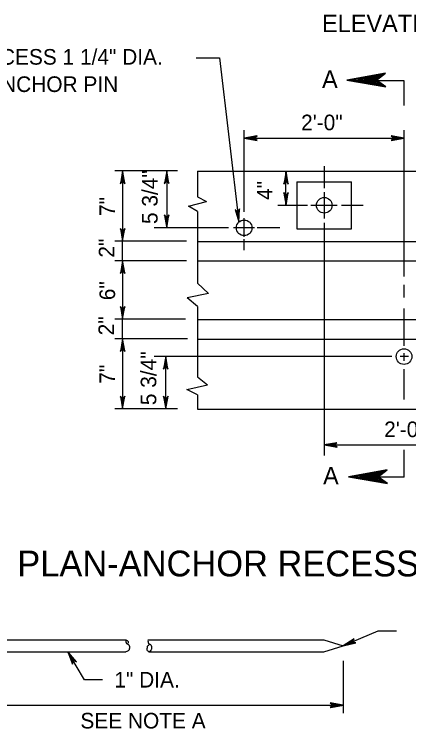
# Model space of a CAD drawing. Extents: x 499883 to 500983, y 499104 to 499764.
# Drawn here: x 500034.1 to 500135.2, y 499385.9 to 499568.8 of the extents above; entities that cross this region are included whole.
import ezdxf

# ---------------------------------------------------------------- set-up
doc = ezdxf.new("R2010")
doc.units = 0
doc.layers.add('24', color=7, linetype='Continuous')
doc.layers.add('5', color=7, linetype='Continuous')

msp = doc.modelspace()

# ---------------------------------------------------------------- linework, layer by layer
at = {"layer": '24'}
for points in [[(500061.83, 499528.7), (500061.25, 499525.43), (500061.83, 499526.21), (500062.4, 499525.44), (500061.83, 499528.7), (500061.84, 499528.48), (500061.3, 499525.52), (500061.84, 499526.27), (500062.36, 499525.58), (500061.85, 499528.37), (500061.83, 499528.26), (500061.38, 499525.72), (500061.84, 499526.29), (500062.28, 499525.7), (500061.83, 499528.21), (500061.85, 499528.1), (500061.45, 499525.88), (500061.83, 499526.31), (500062.23, 499525.87), (500061.85, 499527.78), (500061.85, 499527.6), (500061.53, 499526.04), (500061.82, 499526.35), (500062.15, 499526.02), (500061.83, 499527.56), (500061.82, 499527.39), (500061.62, 499526.22), (500061.85, 499526.45), (500062.07, 499526.2), (500061.83, 499527.23), (500061.82, 499527.06), (500061.68, 499526.36), (500061.84, 499526.48), (500062.01, 499526.29), (500061.83, 499526.98), (500061.72, 499526.52), (500061.85, 499526.59), (500061.97, 499526.39), (500061.85, 499526.86), (500061.77, 499526.56), (500061.87, 499526.69), (500061.93, 499526.54), (500061.84, 499526.69), (500061.82, 499526.61)], [(500103.72, 499528.63), (500103.13, 499525.31), (500103.72, 499526.1), (500104.29, 499525.32), (500103.72, 499528.63), (500103.72, 499528.41), (500103.17, 499525.4), (500103.72, 499526.16), (500104.25, 499525.46), (500103.73, 499528.29), (500103.72, 499528.18), (500103.26, 499525.6), (500103.72, 499526.18), (500104.17, 499525.59), (500103.71, 499528.13), (500103.73, 499528.02), (500103.33, 499525.77), (500103.71, 499526.2), (500104.12, 499525.76), (500103.73, 499527.7), (500103.73, 499527.51), (500103.41, 499525.93), (500103.71, 499526.24), (500104.04, 499525.91), (500103.72, 499527.48), (500103.71, 499527.3), (500103.5, 499526.11), (500103.73, 499526.34), (500103.96, 499526.09), (500103.72, 499527.14), (500103.7, 499526.97), (500103.56, 499526.26), (500103.72, 499526.37), (500103.9, 499526.18), (500103.71, 499526.88), (500103.6, 499526.42), (500103.73, 499526.49), (500103.86, 499526.28), (500103.73, 499526.77), (500103.66, 499526.46), (500103.76, 499526.59), (500103.82, 499526.44), (500103.72, 499526.59), (500103.71, 499526.51)], [(500103.72, 499519.87), (500104.3, 499523.19), (500103.72, 499522.4), (500103.14, 499523.18), (500103.72, 499519.87), (500103.71, 499520.09), (500104.26, 499523.1), (500103.71, 499522.34), (500103.18, 499523.04), (500103.7, 499520.21), (500103.72, 499520.32), (500104.17, 499522.9), (500103.71, 499522.32), (500103.26, 499522.91), (500103.72, 499520.37), (500103.7, 499520.48), (500104.11, 499522.73), (500103.72, 499522.3), (500103.31, 499522.74), (500103.7, 499520.8), (500103.7, 499520.99), (500104.02, 499522.57), (500103.73, 499522.26), (500103.39, 499522.59), (500103.72, 499521.02), (500103.73, 499521.2), (500103.93, 499522.39), (500103.7, 499522.16), (500103.47, 499522.41), (500103.72, 499521.36), (500103.73, 499521.53), (500103.87, 499522.24), (500103.71, 499522.13), (500103.53, 499522.32), (500103.72, 499521.62), (500103.83, 499522.08), (500103.7, 499522.01), (500103.57, 499522.22), (500103.7, 499521.73), (500103.78, 499522.04), (500103.67, 499521.91), (500103.61, 499522.06), (500103.71, 499521.91), (500103.73, 499521.99)], [(500091.63, 499515.65), (500091.82, 499518.97), (500091.34, 499518.12), (500090.68, 499518.82), (500091.63, 499515.65), (500091.6, 499515.86), (500091.79, 499518.87), (500091.34, 499518.06), (500090.74, 499518.69), (500091.57, 499515.98), (500091.58, 499516.09), (500091.73, 499518.66), (500091.34, 499518.04), (500090.83, 499518.57), (500091.57, 499516.14), (500091.54, 499516.24), (500091.68, 499518.5), (500091.35, 499518.02), (500090.9, 499518.41), (500091.51, 499516.56), (500091.48, 499516.74), (500091.62, 499518.32), (500091.36, 499517.99), (500091, 499518.27), (500091.5, 499516.78), (500091.49, 499516.95), (500091.55, 499518.14), (500091.35, 499517.89), (500091.1, 499518.1), (500091.46, 499517.11), (500091.46, 499517.28), (500091.51, 499517.99), (500091.36, 499517.85), (500091.17, 499518.02), (500091.43, 499517.36), (500091.48, 499517.83), (500091.37, 499517.75), (500091.22, 499517.93), (500091.4, 499517.47), (500091.44, 499517.78), (500091.36, 499517.64), (500091.28, 499517.78), (500091.39, 499517.65), (500091.4, 499517.72)], [(500061.83, 499510.71), (500062.41, 499513.99), (500061.83, 499513.21), (500061.26, 499513.97), (500061.83, 499510.71), (500061.83, 499510.93), (500062.37, 499513.9), (500061.83, 499513.15), (500061.31, 499513.84), (500061.82, 499511.05), (500061.83, 499511.16), (500062.28, 499513.7), (500061.83, 499513.13), (500061.38, 499513.71), (500061.83, 499511.21), (500061.82, 499511.32), (500062.22, 499513.54), (500061.83, 499513.11), (500061.43, 499513.55), (500061.82, 499511.63), (500061.82, 499511.82), (500062.13, 499513.37), (500061.84, 499513.07), (500061.52, 499513.4), (500061.83, 499511.85), (500061.84, 499512.03), (500062.04, 499513.19), (500061.82, 499512.97), (500061.59, 499513.21), (500061.83, 499512.19), (500061.85, 499512.35), (500061.98, 499513.05), (500061.83, 499512.94), (500061.65, 499513.13), (500061.83, 499512.44), (500061.94, 499512.89), (500061.82, 499512.83), (500061.69, 499513.03), (500061.82, 499512.55), (500061.89, 499512.85), (500061.79, 499512.73), (500061.73, 499512.87), (500061.83, 499512.73), (500061.84, 499512.8)], [(500061.83, 499505.72), (500061.25, 499502.44), (500061.83, 499503.23), (500062.4, 499502.46), (500061.83, 499505.72), (500061.84, 499505.5), (500061.3, 499502.54), (500061.84, 499503.29), (500062.36, 499502.59), (500061.85, 499505.38), (500061.83, 499505.27), (500061.38, 499502.73), (500061.84, 499503.3), (500062.28, 499502.72), (500061.83, 499505.22), (500061.85, 499505.12), (500061.45, 499502.9), (500061.83, 499503.33), (500062.23, 499502.89), (500061.85, 499504.8), (500061.85, 499504.61), (500061.53, 499503.06), (500061.82, 499503.36), (500062.15, 499503.04), (500061.83, 499504.58), (500061.82, 499504.41), (500061.62, 499503.24), (500061.85, 499503.46), (500062.07, 499503.22), (500061.83, 499504.25), (500061.82, 499504.08), (500061.68, 499503.38), (500061.84, 499503.5), (500062.01, 499503.3), (500061.83, 499504), (500061.72, 499503.54), (500061.85, 499503.6), (500061.97, 499503.4), (500061.85, 499503.88), (500061.77, 499503.58), (500061.87, 499503.71), (500061.93, 499503.56), (500061.84, 499503.71), (500061.82, 499503.63)], [(500061.83, 499490.73), (500062.41, 499494), (500061.83, 499493.22), (500061.26, 499493.99), (500061.83, 499490.73), (500061.83, 499490.95), (500062.37, 499493.91), (500061.83, 499493.16), (500061.31, 499493.85), (500061.82, 499491.06), (500061.83, 499491.17), (500062.28, 499493.71), (500061.83, 499493.14), (500061.38, 499493.73), (500061.83, 499491.22), (500061.82, 499491.33), (500062.22, 499493.55), (500061.83, 499493.12), (500061.43, 499493.56), (500061.82, 499491.65), (500061.82, 499491.83), (500062.13, 499493.39), (500061.84, 499493.09), (500061.52, 499493.41), (500061.83, 499491.87), (500061.84, 499492.04), (500062.04, 499493.21), (500061.82, 499492.98), (500061.59, 499493.23), (500061.83, 499492.2), (500061.85, 499492.37), (500061.98, 499493.07), (500061.83, 499492.95), (500061.65, 499493.14), (500061.83, 499492.45), (500061.94, 499492.91), (500061.82, 499492.84), (500061.69, 499493.04), (500061.82, 499492.57), (500061.89, 499492.87), (500061.79, 499492.74), (500061.73, 499492.89), (500061.83, 499492.74), (500061.84, 499492.82)], [(500061.83, 499485.73), (500061.25, 499482.46), (500061.83, 499483.24), (500062.4, 499482.48), (500061.83, 499485.73), (500061.84, 499485.52), (500061.3, 499482.55), (500061.84, 499483.3), (500062.36, 499482.61), (500061.85, 499485.4), (500061.83, 499485.29), (500061.38, 499482.75), (500061.84, 499483.32), (500062.28, 499482.73), (500061.83, 499485.24), (500061.85, 499485.13), (500061.45, 499482.91), (500061.83, 499483.34), (500062.23, 499482.9), (500061.85, 499484.82), (500061.85, 499484.63), (500061.53, 499483.08), (500061.82, 499483.38), (500062.15, 499483.05), (500061.83, 499484.6), (500061.82, 499484.42), (500061.62, 499483.25), (500061.85, 499483.48), (500062.07, 499483.23), (500061.83, 499484.26), (500061.82, 499484.1), (500061.68, 499483.39), (500061.84, 499483.51), (500062.01, 499483.32), (500061.83, 499484.01), (500061.72, 499483.55), (500061.85, 499483.62), (500061.97, 499483.42), (500061.85, 499483.9), (500061.77, 499483.6), (500061.87, 499483.72), (500061.93, 499483.58), (500061.84, 499483.72), (500061.82, 499483.65)], [(500061.83, 499467.75), (500062.41, 499471.02), (500061.83, 499470.24), (500061.26, 499471), (500061.83, 499467.75), (500061.83, 499467.96), (500062.37, 499470.93), (500061.83, 499470.18), (500061.31, 499470.87), (500061.82, 499468.08), (500061.83, 499468.19), (500062.28, 499470.73), (500061.83, 499470.16), (500061.38, 499470.75), (500061.83, 499468.24), (500061.82, 499468.35), (500062.22, 499470.57), (500061.83, 499470.14), (500061.43, 499470.58), (500061.82, 499468.67), (500061.82, 499468.85), (500062.13, 499470.41), (500061.84, 499470.1), (500061.52, 499470.43), (500061.83, 499468.88), (500061.84, 499469.06), (500062.04, 499470.23), (500061.82, 499470), (500061.59, 499470.25), (500061.83, 499469.22), (500061.85, 499469.38), (500061.98, 499470.09), (500061.83, 499469.97), (500061.65, 499470.16), (500061.83, 499469.47), (500061.94, 499469.93), (500061.82, 499469.86), (500061.69, 499470.06), (500061.82, 499469.58), (500061.89, 499469.89), (500061.79, 499469.76), (500061.73, 499469.9), (500061.83, 499469.76), (500061.84, 499469.84)], [(500113.51, 499458.54), (500116.79, 499457.96), (500116, 499458.54), (500116.77, 499459.11), (500113.51, 499458.54), (500113.73, 499458.54), (500116.7, 499458), (500115.94, 499458.55), (500116.64, 499459.06), (500113.85, 499458.55), (500113.96, 499458.54), (500116.5, 499458.09), (500115.93, 499458.55), (500116.51, 499458.99), (500114.01, 499458.54), (500114.12, 499458.55), (500116.34, 499458.15), (500115.9, 499458.54), (500116.34, 499458.94), (500114.43, 499458.56), (500114.62, 499458.55), (500116.17, 499458.24), (500115.87, 499458.53), (500116.19, 499458.85), (500114.65, 499458.54), (500114.82, 499458.53), (500115.99, 499458.33), (500115.77, 499458.56), (500116.01, 499458.78), (500114.98, 499458.54), (500115.15, 499458.52), (500115.85, 499458.39), (500115.74, 499458.55), (500115.93, 499458.72), (500115.23, 499458.54), (500115.69, 499458.43), (500115.63, 499458.55), (500115.83, 499458.68), (500115.35, 499458.56), (500115.65, 499458.48), (500115.52, 499458.58), (500115.67, 499458.64), (500115.53, 499458.55), (500115.6, 499458.53)], [(500118.39, 499407.09), (500121.63, 499407.84), (500120.69, 499408.07), (500121.17, 499408.89), (500118.39, 499407.09), (500118.59, 499407.18), (500121.53, 499407.85), (500120.63, 499408.05), (500121.06, 499408.8), (500118.7, 499407.23), (500118.8, 499407.26), (500121.31, 499407.85), (500120.61, 499408.04), (500120.98, 499408.68), (500118.85, 499407.28), (500118.94, 499407.34), (500121.14, 499407.84), (500120.59, 499408.03), (500120.84, 499408.57), (500119.23, 499407.46), (500119.4, 499407.54), (500120.96, 499407.86), (500120.56, 499408.01), (500120.74, 499408.43), (500119.44, 499407.54), (500119.6, 499407.59), (500120.76, 499407.87), (500120.46, 499407.99), (500120.6, 499408.29), (500119.75, 499407.67), (500119.91, 499407.72), (500120.6, 499407.87), (500120.44, 499407.97), (500120.54, 499408.2), (500119.98, 499407.77), (500120.44, 499407.84), (500120.33, 499407.93), (500120.47, 499408.13), (500120.08, 499407.83), (500120.38, 499407.87), (500120.23, 499407.92), (500120.34, 499408.03), (500120.24, 499407.89), (500120.32, 499407.9)], [(500047.83, 499405.59), (500049.02, 499402.4), (500049.12, 499403.39), (500050.02, 499403.01), (500047.83, 499405.59), (500047.95, 499405.4), (500049.01, 499402.51), (500049.1, 499403.45), (500049.92, 499403.11), (500048.02, 499405.3), (500048.06, 499405.2), (500048.98, 499402.72), (500049.09, 499403.46), (500049.79, 499403.18), (500048.09, 499405.15), (500048.16, 499405.07), (500048.96, 499402.9), (500049.07, 499403.48), (500049.65, 499403.3), (500048.32, 499404.79), (500048.42, 499404.63), (500048.94, 499403.09), (500049.05, 499403.51), (500049.5, 499403.39), (500048.42, 499404.59), (500048.5, 499404.43), (500048.93, 499403.29), (500049.02, 499403.61), (500049.34, 499403.51), (500048.59, 499404.29), (500048.67, 499404.14), (500048.91, 499403.45), (500048.99, 499403.63), (500049.24, 499403.56), (500048.72, 499404.07), (500048.87, 499403.61), (500048.94, 499403.73), (500049.16, 499403.62), (500048.8, 499403.98), (500048.89, 499403.67), (500048.91, 499403.84), (500049.04, 499403.74), (500048.88, 499403.82), (500048.91, 499403.74)], [(500118.39, 499391.86), (500115.04, 499392.45), (500115.84, 499391.86), (500115.06, 499391.27), (500118.39, 499391.86), (500118.17, 499391.85), (500115.14, 499392.4), (500115.91, 499391.85), (500115.2, 499391.32), (500118.05, 499391.84), (500117.94, 499391.86), (500115.34, 499392.32), (500115.92, 499391.85), (500115.32, 499391.39), (500117.89, 499391.86), (500117.78, 499391.84), (500115.51, 499392.25), (500115.95, 499391.86), (500115.5, 499391.45), (500117.45, 499391.84), (500117.27, 499391.84), (500115.67, 499392.16), (500115.98, 499391.86), (500115.65, 499391.53), (500117.23, 499391.86), (500117.05, 499391.87), (500115.86, 499392.07), (500116.09, 499391.84), (500115.84, 499391.61), (500116.89, 499391.86), (500116.72, 499391.87), (500116, 499392.01), (500116.12, 499391.85), (500115.92, 499391.67), (500116.63, 499391.86), (500116.16, 499391.97), (500116.23, 499391.84), (500116.03, 499391.71), (500116.51, 499391.84), (500116.21, 499391.92), (500116.34, 499391.81), (500116.19, 499391.75), (500116.33, 499391.85), (500116.26, 499391.86)]]:
    msp.add_lwpolyline(points, dxfattribs=at)
at = {"layer": '5'}
for p, q in [((500133.95, 499551.76), (500123.96, 499551.76)), ((500133.95, 499545.45), (500133.95, 499551.76)), ((500092.98, 499518.26), (500092.98, 499539.12)), ((500133.95, 499501.67), (500133.95, 499539.12)), ((500092.98, 499537.13), (500133.95, 499537.13)), ((500075.88, 499528.7), (500059.85, 499528.7)), ((500061.83, 499528.7), (500061.83, 499510.71)), ((500073.13, 499528.7), (500073.13, 499514.14)), ((500080.99, 499528.63), (500170.92, 499528.63)), ((500080.99, 499528.63), (500080.99, 499522.12)), ((500103.7, 499519.91), (500103.7, 499528.63)), ((500113.51, 499529.9), (500113.51, 499524.3)), ((500106.52, 499525.91), (500120.51, 499525.91)), ((500106.52, 499525.91), (500106.52, 499513.92)), ((500120.51, 499513.92), (500120.51, 499525.91)), ((500113.51, 499523.24), (500113.51, 499516.55)), ((500080.99, 499522.12), (500083.29, 499520.89)), ((500078.68, 499519.67), (500083.29, 499520.89)), ((500080.99, 499518.32), (500078.68, 499519.67)), ((500101.6, 499519.91), (500109.22, 499519.91)), ((500110.07, 499519.91), (500116.85, 499519.91)), ((500117.91, 499519.91), (500123.51, 499519.91)), ((500080.99, 499518.32), (500080.99, 499500)), ((500092.98, 499511.81), (500092.98, 499516.63)), ((500088.97, 499514.14), (500069.93, 499514.14)), ((500095.59, 499514.14), (500090.28, 499514.14)), ((500102.15, 499514.14), (500096.32, 499514.14)), ((500106.52, 499513.92), (500120.51, 499513.92)), ((500113.51, 499515.39), (500113.51, 499455.84)), ((500078.21, 499510.71), (500059.85, 499510.71)), ((500061.83, 499505.76), (500061.83, 499510.71)), ((500080.99, 499510.65), (500170.92, 499510.65)), ((500092.98, 499508.41), (500092.98, 499511.23)), ((500078.21, 499505.72), (500059.85, 499505.72)), ((500061.83, 499505.72), (500061.83, 499490.73)), ((500080.99, 499505.65), (500170.92, 499505.65)), ((500080.99, 499500), (500083.84, 499497.29)), ((500133.95, 499496.26), (500133.95, 499499.57)), ((500083.84, 499497.29), (500078.41, 499496.2)), ((500080.99, 499494.03), (500078.41, 499496.2)), ((500080.99, 499494.03), (500080.99, 499475.98)), ((500133.95, 499483.95), (500133.95, 499493.51)), ((500077.96, 499490.73), (500059.85, 499490.73)), ((500061.83, 499485.73), (500061.83, 499490.73)), ((500080.99, 499490.66), (500170.92, 499490.66)), ((500078.46, 499485.73), (500059.85, 499485.73)), ((500061.83, 499485.73), (500061.83, 499467.75)), ((500080.99, 499485.66), (500170.92, 499485.66)), ((500130.83, 499481.17), (500069.93, 499481.17)), ((500072.88, 499467.75), (500072.88, 499481.24)), ((500135.13, 499481.17), (500132.93, 499481.17)), ((500133.95, 499480.05), (500133.95, 499482.05)), ((500133.95, 499470.15), (500133.95, 499477.95)), ((500080.99, 499475.98), (500083.56, 499473.95)), ((500078.27, 499472.73), (500083.56, 499473.95)), ((500080.99, 499471.37), (500078.27, 499472.73)), ((500080.99, 499471.37), (500080.99, 499467.68)), ((500075.88, 499467.75), (500059.85, 499467.75)), ((500080.99, 499467.68), (500170.92, 499467.68)), ((500113.51, 499458.54), (500155.99, 499458.54)), ((500133.95, 499450.26), (500133.95, 499457.32)), ((500133.95, 499450.26), (500123.96, 499450.26)), ((500020.47, 499408.59), (500062.68, 499408.59)), ((500068.34, 499408.59), (500113.4, 499408.59)), ((500113.4, 499408.59), (500118.39, 499407.09)), ((500113.4, 499405.59), (500118.39, 499407.09)), ((500020.47, 499405.59), (500062.68, 499405.59)), ((500068.55, 499405.59), (500113.4, 499405.59)), ((500118.39, 499403.22), (500118.39, 499389.86)), ((500056.71, 499398.41), (500052.06, 499398.41)), ((500018.97, 499391.86), (500118.39, 499391.86))]:
    msp.add_line(p, q, dxfattribs=at)
for points in [[(500080.64, 499557.71), (500086.7, 499557.71), (500091.63, 499515.65)], [(500119.27, 499551.99), (500129.25, 499550.23), (500126.86, 499551.99), (500129.19, 499553.72), (500119.27, 499551.99), (500119.94, 499552.01), (500128.97, 499550.36), (500126.68, 499552.01), (500128.79, 499553.59), (500120.29, 499552.04), (500120.63, 499551.99), (500128.36, 499550.61), (500126.63, 499552.01), (500128.41, 499553.36), (500120.78, 499551.99), (500121.11, 499552.04), (500127.87, 499550.82), (500126.55, 499551.99), (500127.9, 499553.21), (500122.07, 499552.04), (500122.63, 499552.04), (500127.37, 499551.07), (500126.45, 499551.96), (500127.44, 499552.95), (500122.73, 499551.99), (500123.27, 499551.96), (500126.83, 499551.35), (500126.14, 499552.04), (500126.88, 499552.72), (500123.76, 499551.99), (500124.26, 499551.94), (500126.4, 499551.53), (500126.04, 499552.01), (500126.63, 499552.54), (500124.52, 499551.99), (500125.91, 499551.66), (500125.71, 499552.04), (500126.32, 499552.42), (500124.87, 499552.04), (500125.78, 499551.81), (500125.4, 499552.11), (500125.84, 499552.29), (500125.4, 499552.01), (500125.63, 499551.96)], [(500092.98, 499537.13), (500096.31, 499536.54), (500095.51, 499537.13), (500096.29, 499537.7), (500092.98, 499537.13), (500093.2, 499537.13), (500096.21, 499536.58), (500095.45, 499537.13), (500096.16, 499537.66), (500093.32, 499537.14), (500093.43, 499537.13), (500096.01, 499536.67), (500095.43, 499537.13), (500096.03, 499537.58), (500093.48, 499537.12), (500093.59, 499537.14), (500095.85, 499536.73), (500095.41, 499537.12), (500095.86, 499537.53), (500093.92, 499537.14), (500094.1, 499537.14), (500095.68, 499536.82), (500095.37, 499537.12), (500095.71, 499537.45), (500094.14, 499537.13), (500094.31, 499537.11), (500095.5, 499536.91), (500095.27, 499537.14), (500095.52, 499537.37), (500094.48, 499537.13), (500094.64, 499537.11), (500095.36, 499536.97), (500095.24, 499537.13), (500095.43, 499537.31), (500094.73, 499537.12), (500095.2, 499537.01), (500095.13, 499537.14), (500095.33, 499537.27), (500094.85, 499537.14), (500095.15, 499537.07), (500095.03, 499537.17), (500095.17, 499537.23), (500095.03, 499537.13), (500095.1, 499537.12)], [(500133.95, 499537.13), (500130.63, 499537.71), (500131.42, 499537.13), (500130.65, 499536.55), (500133.95, 499537.13), (500133.73, 499537.12), (500130.72, 499537.67), (500131.48, 499537.12), (500130.78, 499536.59), (500133.61, 499537.11), (500133.5, 499537.13), (500130.92, 499537.58), (500131.5, 499537.12), (500130.91, 499536.67), (500133.45, 499537.13), (500133.34, 499537.11), (500131.09, 499537.52), (500131.52, 499537.13), (500131.08, 499536.72), (500133.02, 499537.11), (500132.83, 499537.11), (500131.25, 499537.43), (500131.56, 499537.13), (500131.23, 499536.8), (500132.8, 499537.13), (500132.62, 499537.14), (500131.43, 499537.34), (500131.66, 499537.11), (500131.41, 499536.88), (500132.46, 499537.13), (500132.29, 499537.14), (500131.58, 499537.28), (500131.69, 499537.12), (500131.5, 499536.94), (500132.2, 499537.13), (500131.74, 499537.24), (500131.81, 499537.11), (500131.6, 499536.98), (500132.09, 499537.11), (500131.78, 499537.18), (500131.91, 499537.08), (500131.76, 499537.02), (500131.91, 499537.12), (500131.83, 499537.13)], [(500073.13, 499528.77), (500072.54, 499525.45), (500073.13, 499526.24), (500073.7, 499525.46), (500073.13, 499528.77), (500073.13, 499528.55), (500072.58, 499525.54), (500073.13, 499526.3), (500073.66, 499525.6), (500073.14, 499528.43), (500073.13, 499528.32), (500072.67, 499525.74), (500073.13, 499526.32), (500073.58, 499525.72), (500073.13, 499528.27), (500073.14, 499528.16), (500072.74, 499525.9), (500073.13, 499526.34), (500073.53, 499525.9), (500073.14, 499527.84), (500073.14, 499527.65), (500072.82, 499526.07), (500073.12, 499526.38), (500073.45, 499526.05), (500073.13, 499527.62), (500073.12, 499527.44), (500072.91, 499526.25), (500073.14, 499526.48), (500073.37, 499526.23), (500073.13, 499527.28), (500073.11, 499527.11), (500072.97, 499526.4), (500073.13, 499526.51), (500073.31, 499526.32), (500073.13, 499527.02), (500073.02, 499526.56), (500073.14, 499526.62), (500073.27, 499526.42), (500073.14, 499526.9), (500073.07, 499526.6), (500073.17, 499526.73), (500073.23, 499526.58), (500073.13, 499526.73), (500073.12, 499526.65)], [(500073.13, 499514.14), (500073.71, 499517.47), (500073.13, 499516.67), (500072.55, 499517.45), (500073.13, 499514.14), (500073.12, 499514.36), (500073.67, 499517.37), (500073.12, 499516.61), (500072.59, 499517.32), (500073.11, 499514.48), (500073.13, 499514.59), (500073.58, 499517.17), (500073.12, 499516.59), (500072.67, 499517.19), (500073.13, 499514.64), (500073.11, 499514.75), (500073.52, 499517.01), (500073.13, 499516.57), (500072.72, 499517.02), (500073.11, 499515.08), (500073.11, 499515.26), (500073.43, 499516.84), (500073.14, 499516.53), (500072.8, 499516.86), (500073.13, 499515.3), (500073.14, 499515.47), (500073.34, 499516.66), (500073.11, 499516.43), (500072.88, 499516.68), (500073.13, 499515.64), (500073.14, 499515.8), (500073.28, 499516.52), (500073.12, 499516.4), (500072.94, 499516.59), (500073.13, 499515.89), (500073.24, 499516.36), (500073.11, 499516.29), (500072.98, 499516.49), (500073.11, 499516.01), (500073.19, 499516.31), (500073.09, 499516.19), (500073.03, 499516.33), (500073.12, 499516.19), (500073.14, 499516.26)], [(500072.88, 499481.24), (500072.29, 499477.91), (500072.88, 499478.71), (500073.46, 499477.93), (500072.88, 499481.24), (500072.88, 499481.02), (500072.34, 499478.01), (500072.89, 499478.77), (500073.41, 499478.06), (500072.9, 499480.9), (500072.88, 499480.79), (500072.42, 499478.21), (500072.89, 499478.79), (500073.34, 499478.19), (500072.88, 499480.74), (500072.9, 499480.63), (500072.49, 499478.37), (500072.88, 499478.81), (500073.28, 499478.36), (500072.9, 499480.3), (500072.9, 499480.12), (500072.57, 499478.54), (500072.87, 499478.85), (500073.2, 499478.51), (500072.88, 499480.08), (500072.87, 499479.91), (500072.67, 499478.72), (500072.9, 499478.95), (500073.12, 499478.7), (500072.88, 499479.74), (500072.86, 499479.58), (500072.73, 499478.86), (500072.89, 499478.98), (500073.06, 499478.79), (500072.88, 499479.49), (500072.77, 499479.02), (500072.9, 499479.09), (500073.02, 499478.89), (500072.9, 499479.37), (500072.82, 499479.07), (500072.92, 499479.19), (500072.98, 499479.05), (500072.89, 499479.19), (500072.87, 499479.12)], [(500072.88, 499467.75), (500073.47, 499471.07), (500072.88, 499470.28), (500072.3, 499471.05), (500072.88, 499467.75), (500072.87, 499467.97), (500073.42, 499470.98), (500072.87, 499470.22), (500072.35, 499470.92), (500072.86, 499468.09), (500072.88, 499468.2), (500073.34, 499470.78), (500072.87, 499470.2), (500072.42, 499470.79), (500072.88, 499468.25), (500072.86, 499468.36), (500073.27, 499470.61), (500072.88, 499470.17), (500072.47, 499470.62), (500072.86, 499468.68), (500072.86, 499468.87), (500073.19, 499470.45), (500072.89, 499470.14), (500072.56, 499470.47), (500072.88, 499468.9), (500072.89, 499469.08), (500073.09, 499470.26), (500072.86, 499470.04), (500072.63, 499470.28), (500072.88, 499469.24), (500072.9, 499469.41), (500073.03, 499470.12), (500072.87, 499470), (500072.69, 499470.2), (500072.88, 499469.5), (500072.99, 499469.96), (500072.86, 499469.89), (500072.73, 499470.1), (500072.86, 499469.61), (500072.94, 499469.92), (500072.84, 499469.79), (500072.78, 499469.94), (500072.87, 499469.79), (500072.89, 499469.87)], [(500119.73, 499450.39), (500129.7, 499448.62), (500127.32, 499450.39), (500129.65, 499452.12), (500119.73, 499450.39), (500120.39, 499450.4), (500129.42, 499448.75), (500127.13, 499450.41), (500129.24, 499451.98), (500120.75, 499450.43), (500121.08, 499450.39), (500128.81, 499449.01), (500127.08, 499450.41), (500128.86, 499451.76), (500121.23, 499450.38), (500121.56, 499450.43), (500128.32, 499449.21), (500127.01, 499450.38), (500128.35, 499451.6), (500122.53, 499450.44), (500123.09, 499450.44), (500127.82, 499449.47), (500126.9, 499450.36), (500127.89, 499451.35), (500123.19, 499450.39), (500123.72, 499450.35), (500127.28, 499449.74), (500126.6, 499450.44), (500127.34, 499451.12), (500124.21, 499450.39), (500124.71, 499450.34), (500126.85, 499449.93), (500126.5, 499450.41), (500127.08, 499450.94), (500124.97, 499450.38), (500126.37, 499450.05), (500126.17, 499450.44), (500126.78, 499450.82), (500125.32, 499450.44), (500126.24, 499450.21), (500125.86, 499450.51), (500126.29, 499450.69), (500125.86, 499450.41), (500126.09, 499450.36)], [(500132.05, 499410.88), (500127.27, 499410.88), (500118.39, 499407.09)], [(500056.71, 499398.41), (500052.06, 499398.41), (500047.83, 499405.59)]]:
    msp.add_lwpolyline(points, dxfattribs=at)
for centre in [(500113.51, 499519.91), (500092.98, 499514.14), (500133.95, 499481.17)]:
    msp.add_circle(centre, 2, dxfattribs=at)
for points in [[(500062.68, 499408.59), (500062.84, 499407.71), (500063.32, 499407.44), (500063.58, 499406.75), (500063.53, 499406.27), (500063.42, 499405.95), (500062.68, 499405.59)], [(500062.68, 499408.59), (500063.21, 499408.19), (500063.26, 499407.82), (500063.05, 499407.6)], [(500068.34, 499408.59), (500068.5, 499407.71), (500068.98, 499407.44), (500069.25, 499406.75), (500069.19, 499406.27), (500069.09, 499405.95), (500068.55, 499405.59)], [(500068.55, 499405.59), (500068.34, 499405.68), (500068.12, 499406.37), (500068.18, 499406.59), (500068.18, 499406.86), (500068.28, 499407.07), (500068.5, 499407.23), (500068.55, 499407.28), (500068.71, 499407.5)]]:
    msp.add_spline(points, degree=3, dxfattribs=at)

# ---------------------------------------------------------------- texts
for s, height, p in [('ELEVATION', 4.5, (500112.94, 499564.26)), ('ANCHOR RECESS 1 1/4" DIA.', 4, (499998.29, 499555.93)), ('A', 4.5, (500112.94, 499549.96)), ('HOLE FOR ANCHOR PIN', 4, (499998.29, 499548.93)), ('2\'-0"', 4, (500107.58, 499539.13)), ('2\'-0"', 4, (500128.86, 499460.54)), ('A', 4.5, (500113.2, 499448.41)), ('PLAN-ANCHOR RECESS/POCKET', 6.6001, (500034.83, 499424.87)), ('1" DIA.', 4, (500059.71, 499396.41)), ('SEE NOTE A', 4, (500051.01, 499385.92))]:
    msp.add_text(s, height=height, dxfattribs=at).set_placement(p)
for s, p in [('5 3/4"', (500070.8, 499515.11)), ('4"', (500100.24, 499521.28)), ('7"', (500059.9, 499517.17)), ('2"', (500059.72, 499506.51)), ('6"', (500059.9, 499495.6)), ('2"', (500059.63, 499486.6)), ('5 3/4"', (500070.46, 499468.72)), ('7"', (500059.9, 499474.21))]:
    msp.add_text(s, height=4, rotation=90, dxfattribs=at).set_placement(p)

doc.saveas('drawing.dxf')
